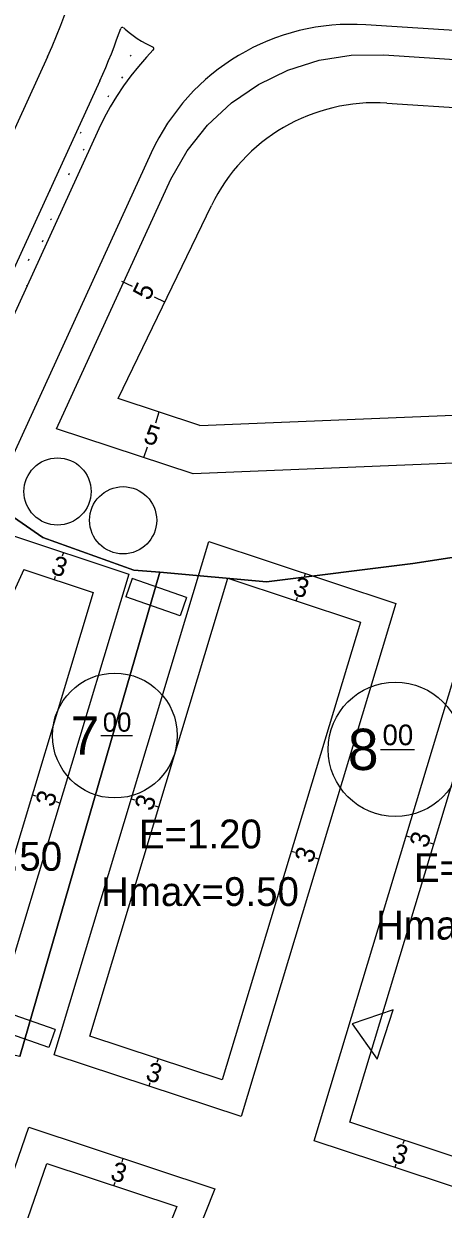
# Model space of a CAD drawing. Extents: x 419396 to 421519, y 4453567 to 4456767.
# Drawn here: x 420984.3 to 421028, y 4454504.3 to 4454627.8 of the extents above; entities that cross this region are included whole.
import ezdxf

# ---------------------------------------------------------------- set-up
doc = ezdxf.new("R2010")
doc.units = 0
for name, color, linetype in [('0_KADASTRO', 7, 'Continuous'), ('Level 16', 7, 'Continuous'), ('Level 20', 7, 'Continuous'), ('Level 28', 7, 'Continuous'), ('Level 29', 7, 'Continuous'), ('Level 30', 7, 'Continuous'), ('Level 41', 7, 'Continuous'), ('Level 53', 7, 'Continuous'), ('Level 55', 7, 'Continuous'), ('Level 58', 7, 'Continuous'), ('Level 62', 7, 'Continuous')]:
    doc.layers.add(name, color=color, linetype=linetype)

msp = doc.modelspace()

# ---------------------------------------------------------------- linework, layer by layer
at = {"layer": '0_KADASTRO'}
for points in [[(421115.84, 4454617.61), (421110.18, 4454569.28), (421098.82, 4454573.19), (421092.11, 4454575.5), (421080.7, 4454577), (421079.93, 4454577.22), (421074.15, 4454578.82), (421073.38, 4454579.02), (421024.86, 4454571.61), (421009.61, 4454569.68), (420998.5, 4454570.68), (420995.77, 4454570.92), (420986.29, 4454574.29), (420978.09, 4454579.98), (420972.54, 4454590.07), (420970.25, 4454598.21), (420978.09, 4454629.67)], [(420983.91, 4454520.25), (420998.5, 4454570.68), (421009.61, 4454569.68), (421024.86, 4454571.61), (421073.38, 4454579.02), (421061.25, 4454538.56), (421060.61, 4454536.72), (421057.52, 4454528.15), (421054.45, 4454520.08), (421051.71, 4454511.49), (421051.38, 4454510.25), (421048.37, 4454500.37)]]:
    msp.add_lwpolyline(points, dxfattribs=at)
msp.add_lwpolyline([(420917.64, 4454527.67), (420938.14, 4454550.22), (420952.33, 4454567.15), (420959.51, 4454575.32), (420972.54, 4454590.07), (420978.09, 4454579.98), (420986.29, 4454574.29), (420995.77, 4454570.92), (420998.5, 4454570.68), (420983.91, 4454520.25), (420965.53, 4454524.31), (420943.17, 4454529.23), (420936.56, 4454515.98)], close=True, dxfattribs=at)
at = {"layer": 'Level 16'}
for p, q in [((421022.81, 4454525.13), (421018.55, 4454523.67)), ((421021.14, 4454519.99), (421022.81, 4454525.13)), ((421018.55, 4454523.67), (421021.14, 4454519.99))]:
    msp.add_line(p, q, dxfattribs=at)
at = {"layer": 'Level 20'}
for p, q in [((421022.16, 4454619.54), (421077.06, 4454615.98)), ((420994.15, 4454588.77), (421003.87, 4454608.88)), ((420994.51, 4454601), (420995.59, 4454600.48)), ((420999.01, 4454598.82), (420997.93, 4454599.35)), ((421002.66, 4454585.96), (420994.15, 4454588.77)), ((421002.66, 4454585.96), (421077.34, 4454589.04)), ((420998.4, 4454587.36), (420998.03, 4454586.22)), ((420996.83, 4454582.62), (420997.21, 4454583.75)), ((420988.44, 4454572.75), (420988.32, 4454572.37)), ((421018.29, 4454513.41), (421035.77, 4454571.32)), ((420984.31, 4454570.96), (420965.89, 4454530.74)), ((420984.31, 4454570.96), (420991.54, 4454568.57)), ((420987.5, 4454569.9), (420987.63, 4454570.28)), ((420991.18, 4454522.38), (421005.58, 4454570.07)), ((421005.58, 4454570.07), (421019.39, 4454565.5)), ((421013.64, 4454570.56), (421013.52, 4454570.18)), ((420991.54, 4454568.57), (420978.84, 4454526.46)), ((421012.7, 4454567.71), (421012.83, 4454568.09)), ((421019.39, 4454565.5), (421004.99, 4454517.81)), ((420985.19, 4454547.51), (420985.57, 4454547.4)), ((420988.06, 4454546.65), (420987.68, 4454546.76)), ((420995.51, 4454547.09), (420995.89, 4454546.97)), ((420998.38, 4454546.22), (420998, 4454546.34)), ((421024.16, 4454543.23), (421024.54, 4454543.12)), ((421012.19, 4454541.65), (421012.58, 4454541.54)), ((421027.03, 4454542.37), (421026.65, 4454542.48)), ((421015.06, 4454540.79), (421014.68, 4454540.9)), ((421004.99, 4454517.81), (420991.18, 4454522.38)), ((420998.31, 4454520.02), (420998.18, 4454519.64)), ((420997.36, 4454517.17), (420997.49, 4454517.55)), ((421030.12, 4454509.49), (421018.29, 4454513.41)), ((421023.95, 4454511.54), (421023.82, 4454511.16)), ((420994.64, 4454509.65), (420994.52, 4454509.26)), ((420958.67, 4454428.51), (420986.71, 4454509.11)), ((420986.71, 4454509.11), (421000.25, 4454504.63)), ((421023.01, 4454508.69), (421023.13, 4454509.07)), ((420993.7, 4454506.8), (420993.83, 4454507.18)), ((421000.25, 4454504.63), (420968.57, 4454425.07))]:
    msp.add_line(p, q, dxfattribs=at)
msp.add_arc((421020.93, 4454600.63), 18.95, 86.2833, 154.2067, dxfattribs=at)
at = {"layer": 'Level 28'}
for p, q in [((420982.7, 4454574.65), (420995.26, 4454570.5)), ((421003.59, 4454573.88), (421023.1, 4454567.43))]:
    msp.add_line(p, q, dxfattribs=at)
at = {"layer": 'Level 29'}
for p, q in [((421015.08, 4454624.01), (421018.44, 4454624.54)), ((421018.44, 4454624.54), (421021.84, 4454624.58)), ((421021.84, 4454624.58), (421082.01, 4454620.67)), ((421011.83, 4454622.99), (421015.08, 4454624.01)), ((421008.77, 4454621.49), (421011.83, 4454622.99)), ((421005.96, 4454619.57), (421008.77, 4454621.49)), ((421003.47, 4454617.24), (421005.96, 4454619.57)), ((421001.35, 4454614.58), (421003.47, 4454617.24)), ((420999.65, 4454611.63), (421001.35, 4454614.58)), ((420987.73, 4454585.63), (420999.65, 4454611.63)), ((421001.95, 4454580.92), (420987.73, 4454585.63)), ((421079.73, 4454584.13), (421001.95, 4454580.92)), ((421014.57, 4454511.48), (421033.79, 4454575.14)), ((420987.47, 4454520.44), (421003.59, 4454573.88)), ((420995.26, 4454570.5), (420980.82, 4454522.64)), ((421023.1, 4454567.43), (421006.98, 4454513.99)), ((421006.98, 4454513.99), (420987.47, 4454520.44)), ((420954.85, 4454426.67), (420984.85, 4454512.88)), ((420984.85, 4454512.88), (421004.22, 4454506.48)), ((421032.1, 4454505.68), (421014.57, 4454511.48)), ((421004.22, 4454506.48), (420970.29, 4454421.29))]:
    msp.add_line(p, q, dxfattribs=at)
at = {"layer": 'Level 41'}
for p, q in [((420995.39, 4454624.53), (420995.46, 4454624.42)), ((420994.54, 4454622.13), (420994.62, 4454622.29)), ((420993.11, 4454620.19), (420993.18, 4454620.35)), ((420990.23, 4454616.4), (420990.3, 4454616.56)), ((420990.49, 4454614.76), (420990.56, 4454614.65)), ((420989.02, 4454612.09), (420989.09, 4454612.25)), ((420987.04, 4454610.53), (420987.1, 4454610.43)), ((420989.13, 4454610.35), (420989.15, 4454610.33)), ((420987.1, 4454607.51), (420987.17, 4454607.4)), ((420986.25, 4454605.11), (420986.32, 4454605.27)), ((420984.81, 4454603.17), (420984.88, 4454603.33)), ((420984.58, 4454600.58), (420984.64, 4454600.49))]:
    msp.add_line(p, q, dxfattribs=at)
at = {"layer": 'Level 53'}
for p, q in [((420995.59, 4454570.03), (420994.93, 4454568.14)), ((421001.26, 4454568.05), (420995.59, 4454570.03)), ((421000.6, 4454566.16), (420994.93, 4454568.14)), ((421001.26, 4454568.05), (421000.6, 4454566.16)), ((420987.58, 4454523.07), (420981.91, 4454525.05)), ((420986.92, 4454521.18), (420981.25, 4454523.16)), ((420987.58, 4454523.07), (420986.92, 4454521.18))]:
    msp.add_line(p, q, dxfattribs=at)
at = {"layer": 'Level 55'}
for centre in [(420987.83, 4454579.1), (420994.66, 4454576.1)]:
    msp.add_circle(centre, 3.5, dxfattribs=at)
at = {"layer": 'Level 58'}
for p, q in [((420992.35, 4454553.68), (420995.65, 4454553.68)), ((421021.48, 4454552.24), (421025.03, 4454552.24))]:
    msp.add_line(p, q, dxfattribs=at)
for centre, radius in [((420993.8, 4454553.68), 6.5), ((421023.04, 4454552.24), 7)]:
    msp.add_circle(centre, radius, dxfattribs=at)
at = {"layer": 'Level 62'}
for p, q in [((420993.99, 4454626.13), (420994.25, 4454626.85)), ((420994.25, 4454626.85), (420994.41, 4454627.32)), ((420994.72, 4454627.39), (420994.88, 4454627.24)), ((420994.88, 4454627.24), (420995.29, 4454626.9)), ((420995.29, 4454626.9), (420995.71, 4454626.58)), ((421081.36, 4454623.72), (421019.95, 4454627.71)), ((420993.72, 4454625.41), (420993.99, 4454626.13)), ((420995.71, 4454626.58), (420996.14, 4454626.28)), ((420996.14, 4454626.28), (420996.59, 4454626)), ((420996.59, 4454626), (420997.04, 4454625.74)), ((420997.04, 4454625.74), (420997.51, 4454625.5)), ((420986.78, 4454624.36), (420904.67, 4454445.13)), ((420993.15, 4454623.98), (420993.44, 4454624.69)), ((420993.44, 4454624.69), (420993.72, 4454625.41)), ((420997.1, 4454624.34), (420996.25, 4454623.37)), ((420997.8, 4454625.08), (420997.1, 4454624.34)), ((420997.51, 4454625.5), (420997.74, 4454625.39)), ((420992.55, 4454622.56), (420992.85, 4454623.27)), ((420992.85, 4454623.27), (420993.15, 4454623.98)), ((420996.25, 4454623.37), (420995.45, 4454622.37)), ((420992.23, 4454621.86), (420910.12, 4454442.63)), ((420992.23, 4454621.86), (420992.55, 4454622.56)), ((420995.45, 4454622.37), (420994.69, 4454621.33)), ((420994.69, 4454621.33), (420993.98, 4454620.25)), ((420993.98, 4454620.25), (420993.32, 4454619.15)), ((420993.32, 4454619.15), (420992.7, 4454618.02)), ((420992.7, 4454618.02), (420992.14, 4454616.86)), ((420992.14, 4454616.86), (420911.77, 4454441.42)), ((420997.6, 4454614.36), (420917.22, 4454438.92))]:
    msp.add_line(p, q, dxfattribs=at)
for centre, radius, start, end in [((420937.34, 4454647), 54.38, 335.3866, 15.3875), ((420994.59, 4454627.25), 0.187, 47.8964, 160.8693), ((421018.46, 4454604.8), 22.95, 86.2833, 155.3866), ((420997.66, 4454625.21), 0.195, 316.2821, 64.9183)]:
    msp.add_arc(centre, radius, start, end, dxfattribs=at)

# ---------------------------------------------------------------- texts
at = {"layer": 'Level 20'}
for s, rotation, p in [('5', 64.2067, (420997.37, 4454598.88)), ('5', 341.6948, (420996.67, 4454584.25)), ('3', 341.6948, (420987.03, 4454570.59)), ('3', 341.6948, (421012.22, 4454568.4)), ('3', 73.2061, (420987.39, 4454546.15)), ('3', 73.2061, (420997.71, 4454545.73)), ('3', 73.2061, (421026.36, 4454541.87)), ('3', 73.2061, (421014.39, 4454540.29)), ('3', 341.6948, (420996.89, 4454517.86)), ('3', 341.6948, (421022.53, 4454509.37)), ('3', 341.6948, (420993.22, 4454507.48))]:
    msp.add_text(s, height=2, rotation=rotation, dxfattribs=at).set_placement(p)
at = {"layer": 'Level 30'}
for s, p in [('E=1.20', (420996.3, 4454541.93)), ('Hmax=9.50', (420967.68, 4454539.6)), ('E=1.20', (421024.96, 4454538.43)), ('Hmax=9.50', (420992.36, 4454535.93)), ('Hmax=9.50', (421021.02, 4454532.43))]:
    msp.add_text(s, height=3, dxfattribs=at).set_placement(p)
at = {"layer": 'Level 58'}
for s, height, p in [('7', 4, (420989.2, 4454551.69)), ('00', 1.998, (420992.55, 4454554.08)), ('8', 4.3, (421018.09, 4454550.09)), ('00', 2.152, (421021.7, 4454552.67))]:
    msp.add_text(s, height=height, dxfattribs=at).set_placement(p)

doc.saveas('drawing.dxf')
